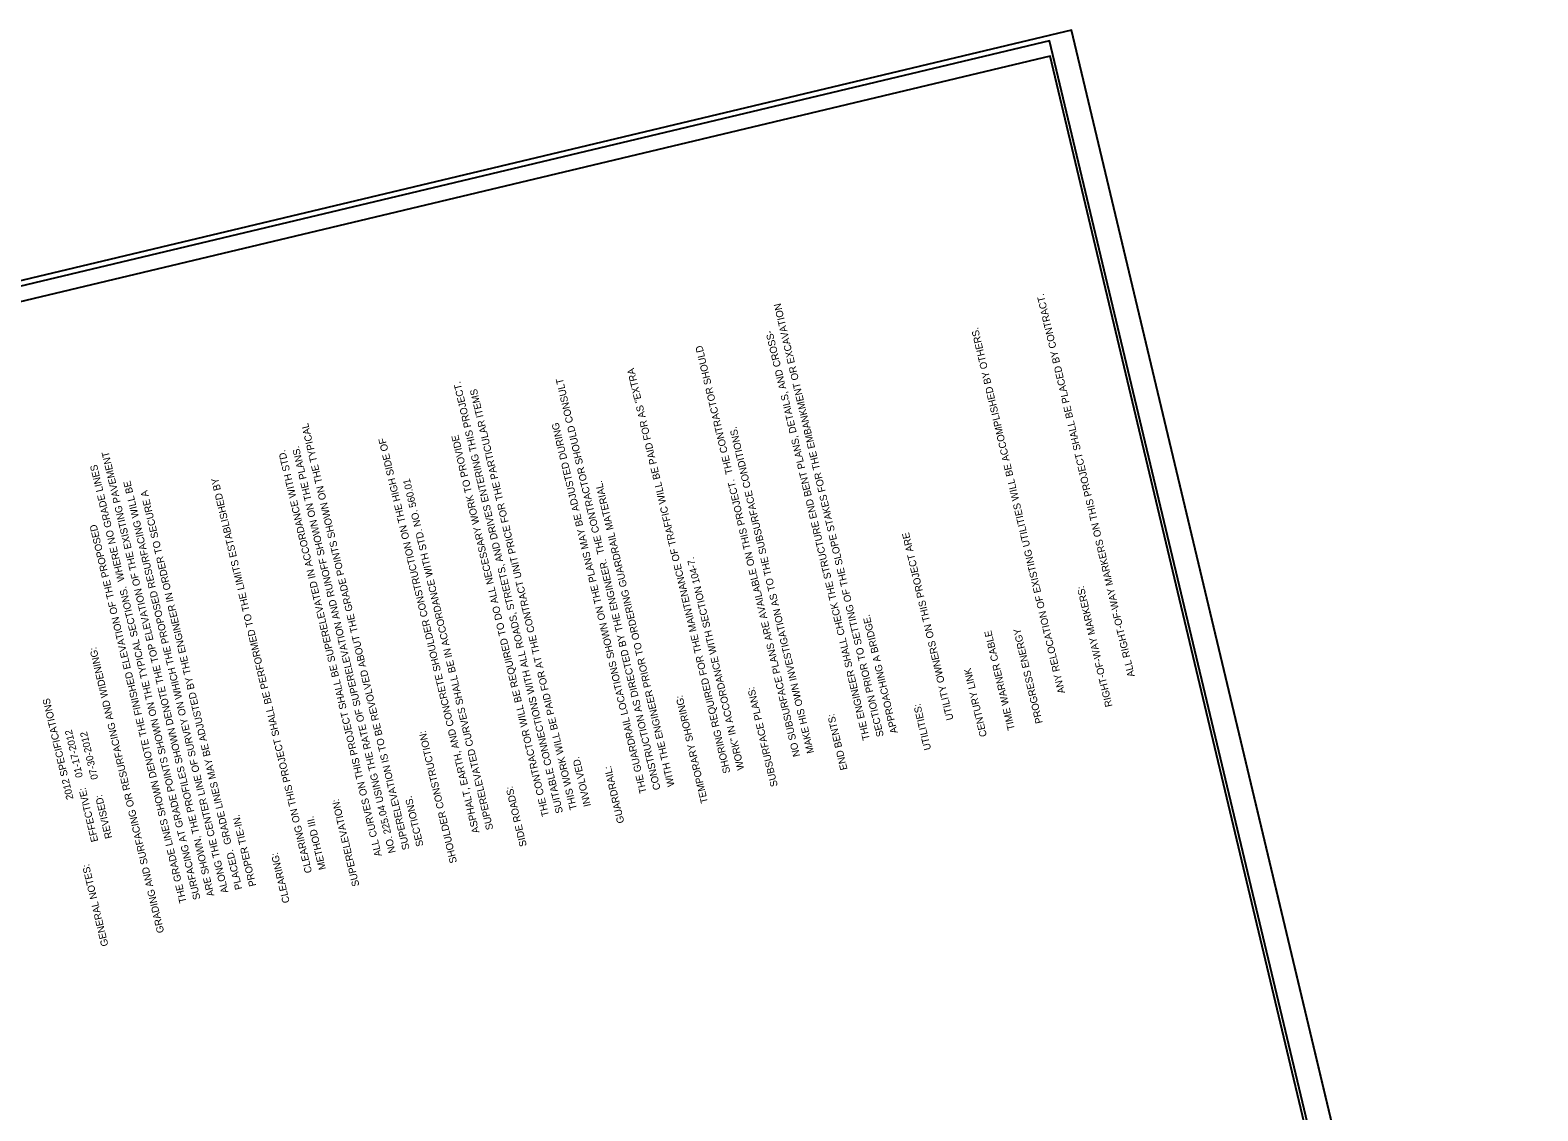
# Model space of a CAD drawing. Extents: x 1734738 to 1742883, y 698103 to 703125.
# Drawn here: x 1740359 to 1742883, y 701316 to 703125 of the extents above; entities that cross this region are included whole.
import ezdxf

# ---------------------------------------------------------------- set-up
doc = ezdxf.new("R2010")
doc.units = 0
for name, color, linetype in [('Default', 7, 'Continuous'), ('Exist Road Primary US Structure Standard Bridge Number Label', 7, 'Continuous'), ('Exist Road Secondary Structure Pipe Number Label', 7, 'Continuous'), ('Exist Road Secondary Type 41 SR Number Label', 7, 'Continuous'), ('Map Preparation County Base Positioning Point', 7, 'Continuous')]:
    doc.layers.add(name, color=color, linetype=linetype)

msp = doc.modelspace()

# ---------------------------------------------------------------- linework, layer by layer
at = {"layer": 'Exist Road Primary US Structure Standard Bridge Number Label'}
msp.add_line((1742882.7, 699849.5), (1742102.1, 703124.7), dxfattribs=at)
at = {"layer": 'Exist Road Secondary Structure Pipe Number Label'}
msp.add_lwpolyline([(1742837.8, 699865.5), (1742065.3, 703106.7), (1740012.8, 702617.5), (1740785.3, 699376.3)], close=True, dxfattribs=at)
at = {"layer": 'Exist Road Secondary Type 41 SR Number Label'}
msp.add_lwpolyline([(1742882.7, 699849.5), (1742102.1, 703124.7), (1739971.8, 702617), (1740752.4, 699341.7)], close=True, dxfattribs=at)
at = {"layer": 'Map Preparation County Base Positioning Point'}
msp.add_lwpolyline([(1740023.4, 702594.3), (1740719, 699676.1), (1742761.7, 700163), (1742066.2, 703081.2)], close=True, dxfattribs=at)

# ---------------------------------------------------------------- texts
at = {"layer": 'Default'}
for s, p in [('         ALL RIGHT-OF-WAY MARKERS ON THIS PROJECT SHALL BE PLACED BY CONTRACT.  ', (1742217.3, 702004.6)), ('         SECTION PRIOR TO SETTING OF THE SLOPE STAKES FOR THE EMBANKMENT OR EXCAVATION ', (1741797.1, 701904.4)), ('         THE ENGINEER SHALL CHECK THE STRUCTURE END BENT PLANS, DETAILS, AND CROSS-', (1741773.7, 701898.9)), ('         ANY RELOCATION OF EXISTING UTILITIES WILL BE ACCOMPLISHED BY OTHERS.  ', (1742100.6, 701976.8)), ('         NO SUBSURFACE PLANS ARE AVAILABLE ON THIS PROJECT.  THE CONTRACTOR SHOULD ', (1741657, 701871)), ('         SHORING REQUIRED FOR THE MAINTENANCE OF TRAFFIC WILL BE PAID FOR AS "EXTRA ', (1741540.2, 701843.2)), ('         SUITABLE CONNECTIONS WITH ALL ROADS, STREETS, AND DRIVES ENTERING THIS PROJECT.  ', (1741260.1, 701776.4)), ('         THIS WORK WILL BE PAID FOR AT THE CONTRACT UNIT PRICE FOR THE PARTICULAR ITEMS ', (1741283.4, 701782)), ('         CONSTRUCTION AS DIRECTED BY THE ENGINEER.  THE CONTRACTOR SHOULD CONSULT', (1741423.5, 701815.4)), ('         SUPERELEVATION IS TO BE REVOLVED ABOUT THE GRADE POINTS SHOWN ON THE TYPICAL ', (1741003.3, 701715.2)), ('         THE GUARDRAIL LOCATIONS SHOWN ON THE PLANS MAY BE ADJUSTED DURING ', (1741400.2, 701809.8)), ('         ASPHALT, EARTH, AND CONCRETE SHOULDER CONSTRUCTION ON THE HIGH SIDE OF', (1741120, 701743.1)), ('         THE CONTRACTOR WILL BE REQUIRED TO DO ALL NECESSARY WORK TO PROVIDE ', (1741236.7, 701770.9)), ('         MAKE HIS OWN INVESTIGATION AS TO THE SUBSURFACE CONDITIONS.  ', (1741680.3, 701876.6)), ('         ARE SHOWN, THE PROFILES SHOWN DENOTE THE TOP ELEVATION OF THE EXISTING PAVEMENT ', (1740676.4, 701637.3)), ('         ALL CURVES ON THIS PROJECT SHALL BE SUPERELEVATED IN ACCORDANCE WITH STD. ', (1740956.6, 701704.1)), ('         NO. 225.04 USING THE RATE OF SUPERELEVATION AND RUNOFF SHOWN ON THE PLANS.', (1740979.9, 701709.7)), ('         SURFACING AT GRADE POINTS SHOWN ON THE TYPICAL SECTIONS.  WHERE NO GRADE LINES ', (1740653.1, 701631.8)), ('         ALONG THE CENTER LINE OF SURVEY ON WHICH THE PROPOSED RESURFACING WILL BE ', (1740699.8, 701642.9)), ('         CLEARING ON THIS PROJECT SHALL BE PERFORMED TO THE LIMITS ESTABLISHED BY ', (1740839.9, 701676.3)), ('         SUPERELEVATED CURVES SHALL BE IN ACCORDANCE WITH STD. NO. 560.01', (1741143.4, 701748.6)), ('         WITH THE ENGINEER PRIOR TO ORDERING GUARDRAIL MATERIAL.', (1741446.9, 701821)), ('         PLACED.  GRADE LINES MAY BE ADJUSTED BY THE ENGINEER IN ORDER TO SECURE A ', (1740723.1, 701648.5)), ('         THE GRADE LINES SHOWN DENOTE THE FINISHED ELEVATION OF THE PROPOSED ', (1740629.8, 701626.2)), ('         UTILITY OWNERS ON THIS PROJECT ARE ', (1741913.8, 701932.2)), ('         WORK" IN ACCORDANCE WITH SECTION 104-7.  ', (1741563.6, 701848.8)), ('RIGHT-OF-WAY MARKERS:  ', (1742170.6, 701993.4)), ('         APPROACHING A BRIDGE.  ', (1741820.4, 701910)), ('TIME WARNER CABLE', (1742007.2, 701954.5)), ('PROGRESS ENERGY', (1742053.9, 701965.6)), ('GRADING AND SURFACING OR RESURFACING AND WIDENING:  ', (1740583.1, 701615.1)), ('CENTURY LINK', (1741960.5, 701943.4)), ('SUBSURFACE PLANS:  ', (1741610.3, 701859.9)), ('GENERAL NOTES:                         2012 SPECIFICATIONS', (1740489.7, 701592.8)), ('TEMPORARY SHORING:  ', (1741493.6, 701832.1)), ('UTILITIES:  ', (1741867.1, 701921.1)), ('END BENTS:  ', (1741727, 701887.7)), ('                                       EFFECTIVE:    01-17-2012', (1740513, 701598.4)), ('                                       REVISED:      07-30-2012', (1740536.4, 701603.9)), ('SHOULDER CONSTRUCTION:  ', (1741073.3, 701731.9)), ('         INVOLVED.  ', (1741306.8, 701787.6)), ('GUARDRAIL:  ', (1741353.5, 701798.7)), ('SUPERELEVATION:  ', (1740909.9, 701693)), ('         SECTIONS.  ', (1741026.6, 701720.8)), ('SIDE ROADS:  ', (1741190.1, 701759.7)), ('         PROPER TIE-IN.  ', (1740746.5, 701654)), ('         METHOD III.', (1740863.2, 701681.8)), ('CLEARING:  ', (1740793.2, 701665.2))]:
    msp.add_text(s, height=12, rotation=103.4059, dxfattribs=at).set_placement(p)

doc.saveas('drawing.dxf')
